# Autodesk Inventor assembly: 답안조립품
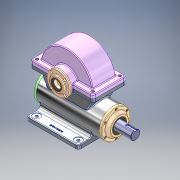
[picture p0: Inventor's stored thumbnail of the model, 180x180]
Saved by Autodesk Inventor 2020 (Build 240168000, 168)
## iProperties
Created: 2023-07
Part Number: 답안조립품
Document SubType Name: Assembly
Designer: com
Author: com
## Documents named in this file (14)
- C:\Users\com\Desktop\730706V1015\답안조립품.iam
- C:\Users\com\Desktop\730706V1015\본체.ipt
- C:\Users\com\Desktop\730706V1015\웜 휠.ipt
- C:\Users\com\Desktop\730706V1015\웜 샤프트.ipt
- C:\Users\com\Desktop\730706V1015\깊은 홈 볼 베어링 6209.ipt
- C:\Users\com\Desktop\730706V1015\깊은 홈 볼 베어링 6206.ipt
- C:\Users\com\Desktop\730706V1015\본체 커버.ipt
- C:\Users\com\Desktop\730706V1015\육각 소켓 머리 볼트 M6 x 20.ipt
- C:\Users\com\Desktop\730706V1015\서브커버.ipt
- C:\Users\com\Desktop\730706V1015\오일 실 30 42 7.ipt
- C:\Users\com\Desktop\730706V1015\앞커버.ipt
- C:\Users\com\Desktop\730706V1015\뒤커버.ipt
- C:\Users\com\Desktop\730706V1015\육각 소켓 머리 볼트 M5 x 12.ipt
- C:\Users\com\Desktop\730706V1015\오일 실 35 55 11.ipt
